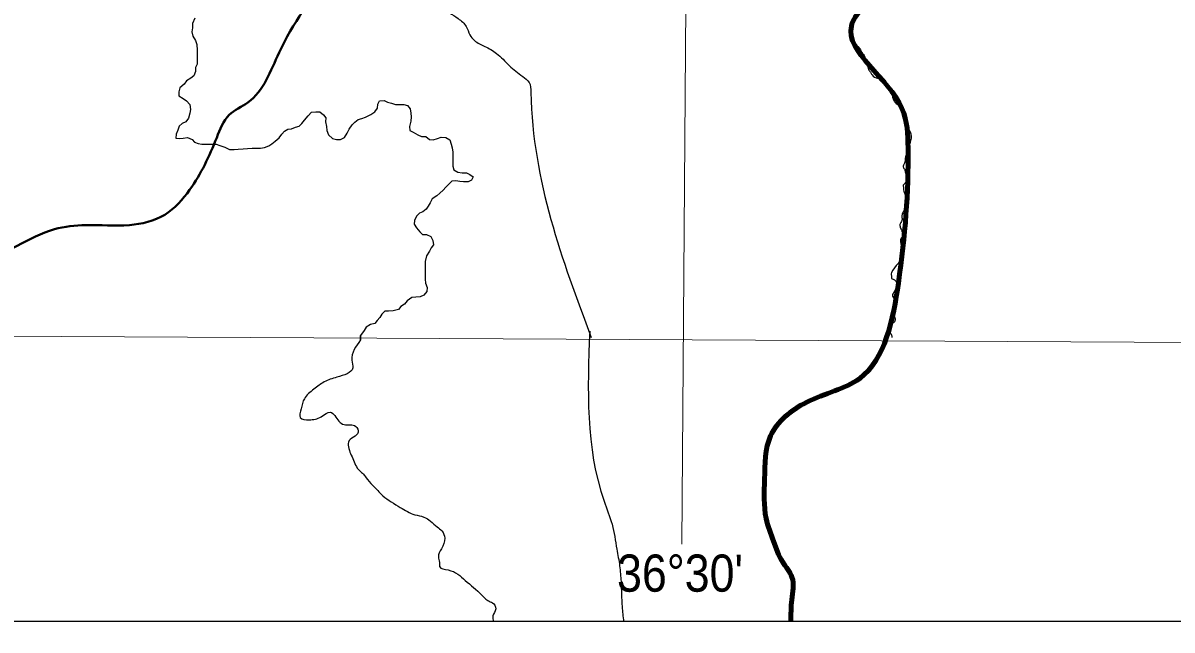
# Model space of a CAD drawing. Extents: x -1643653 to 4543381, y 1624270 to 13878484.
# Drawn here: x 765192 to 780645, y 8889723 to 8897887 of the extents above; entities that cross this region are included whole.
import ezdxf
from ezdxf.enums import TextEntityAlignment as Align

# ---------------------------------------------------------------- set-up
doc = ezdxf.new("R2010")
doc.units = 0
doc.header["$LTSCALE"] = 200
for name, color, linetype, lineweight in [('1', 7, 'Continuous', 13), ('12', 7, 'Continuous', 25), ('24', 7, 'Continuous', 25), ('3', 7, 'Continuous', 13), ('57', 7, 'Continuous', 13), ('60', 7, 'Continuous', 13), ('9', 7, 'Continuous', 90)]:
    doc.layers.add(name, color=color, linetype=linetype, lineweight=lineweight)
doc.layers.add('46', color=7, linetype='Continuous')

msp = doc.modelspace()

# ---------------------------------------------------------------- linework, layer by layer
at = {"layer": '1'}
for points in [[(774987.1, 9020818), (774482.3, 8948876), (774053.6, 8890875.3)], [(564751.7, 8894587.5), (664411.9, 8894209.9), (791388.5, 8893536.2)]]:
    msp.add_lwpolyline(points, dxfattribs=at)
at = {"layer": '12', "lineweight": 40}
msp.add_spline([(762623.9, 8893658.6), (765112.7, 8894889), (765616.1, 8895112.7), (766035.6, 8895168.6), (766622.8, 8895168.6), (767098.2, 8895308.5), (767433.8, 8895644), (767797.3, 8896343.2), (767965.1, 8896650.8), (768216.8, 8896818.6), (768636.3, 8897489.7), (769335.4, 8898552.4), (769698.9, 8899027.8), (770118.4, 8899810.8), (770454, 8900314.2), (770957.3, 8900677.7), (771712.4, 8900845.5), (772663.2, 8901013.3), (773474.2, 8900985.3), (774089.4, 8900957.3), (774760.5, 8900621.8), (775208, 8900454), (775431.7, 8900426), (775851.2, 8900733.6), (776242.7, 8901013.3), (776578.2, 8900985.3), (777025.7, 8900873.4), (777193.5, 8900929.4), (777277.3, 8901125.1), (777221.4, 8901460.7), (777277.3, 8901964.1), (777221.4, 8902439.5), (777081.6, 8902691.1), (777165.5, 8902914.9), (777417.2, 8903474.2), (777836.6, 8904201.2), (778228.2, 8904648.7), (778591.7, 8904956.3), (779254.3, 8905013.8), (779906, 8904928.3), (780814.8, 8904826.8)], degree=3, dxfattribs=at)
at = {"layer": '12'}
for points in [[(769589.5, 8898862.9), (770301.2, 8898417.1), (770809.5, 8898096.4), (771044.1, 8897947.8), (771153.6, 8897838.3), (771200.5, 8897728.9), (771263.1, 8897650.7), (771403.9, 8897572.4), (771560.3, 8897478.6), (771732.4, 8897314.4), (771912.2, 8897165.8), (771998.3, 8897087.6), (772021.7, 8896954.6), (772834.8, 8893656.6)], [(772814, 8893741.2), (773007.1, 8891454.9), (773113.6, 8891144.6), (773178.4, 8890810.2), (773216.5, 8890584.1), (773234.7, 8890374.1), (773248.5, 8890036.5), (773269.9, 8889836.8)]]:
    msp.add_spline(points, degree=3, dxfattribs=at)
at = {"layer": '24'}
for points in [[(767502.1, 8897951.1), (767471.1, 8897880), (767470.7, 8897824), (767465.2, 8897768), (767475, 8897711.9), (767510.2, 8897650.6), (767530.2, 8897599.5), (767534.8, 8897523), (767534.4, 8897461.9), (767533.9, 8897395.7), (767533.5, 8897334.6), (767512.8, 8897288.9)], [(767512.8, 8897288.9), (767512.4, 8897232.8), (767488, 8897175.6), (767450.1, 8897147.2), (767389.5, 8897111.4), (767358.7, 8897065.7), (767302.4, 8897015.2), (767286.8, 8896959.2), (767286.4, 8896908.3), (767347.2, 8896872.2), (767392.8, 8896841.4), (767438.2, 8896790.2), (767442.8, 8896723.9), (767437.4, 8896673), (767416.6, 8896606.9), (767380.6, 8896556.2), (767334.7, 8896536.1), (767293.8, 8896500.7), (767273.1, 8896444.8), (767252.4, 8896394), (767246.9, 8896338), (767297.7, 8896332.6), (767348.6, 8896337.4), (767404.6, 8896347.2), (767465.5, 8896321.3), (767500.8, 8896285.4), (767546.5, 8896264.8), (767597.3, 8896259.4), (767668.5, 8896258.9), (767719.4, 8896258.6), (767790.6, 8896258.1), (767841.3, 8896237.4), (767907.3, 8896216.6), (767968.1, 8896185.7), (768034.2, 8896185.2), (768085.1, 8896190), (768151.2, 8896194.7)], [(768151.2, 8896194.7), (768212.3, 8896199.4), (768273.4, 8896204.1), (768329.3, 8896203.7), (768385.3, 8896203.4), (768441.3, 8896213.2), (768497.4, 8896233.2), (768538.3, 8896263.5), (768584.3, 8896298.9), (768635.5, 8896344.4), (768671.4, 8896390), (768707.3, 8896430.5), (768753.2, 8896460.8), (768804.1, 8896465.6), (768855.1, 8896485.6), (768906.1, 8896500.6), (768942, 8896536), (768977.9, 8896581.6), (769029.1, 8896637.3), (769070.2, 8896688), (769131.2, 8896692.7), (769182.1, 8896692.4), (769232.7, 8896651.3), (769262.9, 8896610.3), (769262.5, 8896559.4), (769272.3, 8896493.1), (769277, 8896442.2), (769302, 8896380.9), (769352.6, 8896334.7), (769408.4, 8896319.1), (769464.3, 8896318.7), (769515.4, 8896348.9), (769551.4, 8896404.7), (769577.2, 8896460.6), (769618.3, 8896516.4), (769654.1, 8896551.8), (769700.1, 8896587.2), (769751.1, 8896602.1), (769797, 8896622.2), (769868.5, 8896657.4), (769924.7, 8896692.7), (769960.6, 8896743.4), (769966.1, 8896794.3), (769986.7, 8896840), (770047.8, 8896844.7), (770093.4, 8896824.1), (770149.2, 8896808.4), (770200, 8896792.8), (770256, 8896792.4), (770311.9, 8896792.1), (770362.7, 8896776.5), (770397.9, 8896730.4), (770407.7, 8896674.3), (770412.5, 8896623.3), (770407, 8896567.3), (770391.2, 8896496.1), (770395.9, 8896440.1), (770441.6, 8896419.4), (770502.4, 8896383.4), (770553.1, 8896362.7), (770609, 8896362.3), (770659.6, 8896321.2), (770710.4, 8896315.8), (770766.5, 8896335.8), (770817.5, 8896350.8)], [(770817.5, 8896350.8), (770878.5, 8896345.3), (770934.2, 8896314.4), (770949.1, 8896258.2), (770964, 8896207.2), (770973.8, 8896151.1), (770973.3, 8896079.8), (770972.9, 8896023.8), (770972.5, 8895962.7), (770987.4, 8895911.6), (771038, 8895880.7), (771099, 8895870.2), (771154.9, 8895869.8), (771200.6, 8895849.1), (771246.1, 8895818.3), (771225.5, 8895772.6), (771179.6, 8895752.5), (771118.5, 8895752.9), (771067.7, 8895753.2), (771011.8, 8895763.7), (770960.9, 8895759), (770914.8, 8895713.4), (770879, 8895678), (770843.1, 8895637.5), (770797, 8895597), (770756.1, 8895561.6), (770694.8, 8895521.3), (770669, 8895470.5), (770643.3, 8895424.8), (770612.5, 8895384.3), (770571.5, 8895348.9), (770525.6, 8895328.8), (770484.7, 8895288.3), (770458.8, 8895232.4), (770453.4, 8895181.5), (770483.6, 8895130.4), (770529, 8895079.2)], [(770529, 8895079.2), (770564.3, 8895043.3), (770620.3, 8895042.9), (770676.1, 8895017.1), (770706.2, 8894960.9), (770710.9, 8894904.8), (770680.1, 8894864.2), (770659.4, 8894818.5), (770618.3, 8894757.7), (770602.6, 8894681.4), (770602.1, 8894620.2), (770601.7, 8894559.1), (770601.3, 8894498), (770600.9, 8894442), (770605.6, 8894385.9), (770625.6, 8894329.8), (770625.2, 8894273.7), (770584.2, 8894228.1), (770533.1, 8894203), (770477.2, 8894198.3), (770421.2, 8894193.5), (770359.8, 8894148.1), (770324, 8894107.6), (770272.8, 8894072.2), (770242.1, 8894031.7), (770170.7, 8894016.8), (770109.7, 8894012.1), (770058.8, 8894012.5), (770017.8, 8893972), (769992.1, 8893926.3), (769956.2, 8893885.8), (769925.4, 8893845.2), (769864.3, 8893830.3), (769808.1, 8893795), (769782.3, 8893749.4), (769731, 8893683.5), (769730.6, 8893623.6), (769730.6, 8893623.6), (769731, 8893683.5)]]:
    msp.add_lwpolyline(points, dxfattribs=at)
for points in [[(776365.9, 8897887.4), (776337, 8897852.2), (776322, 8897817.1), (776310.7, 8897755.6), (776314.5, 8897724.2), (776345.8, 8897655.4), (776379.7, 8897601.5), (776422.3, 8897570.1), (776466.2, 8897507.3), (776502.6, 8897448.3), (776539, 8897370.5), (776552.8, 8897306.5), (776564.1, 8897265.1), (776587.9, 8897223.7), (776611.8, 8897188.5), (776684.5, 8897143.3), (776759.8, 8897134.6), (776784.9, 8897119.5), (776803.7, 8897075.6), (776837.6, 8897037.9), (776875.2, 8896999), (776882.7, 8896955.1), (776887.8, 8896884.8), (776899.1, 8896853.4), (776925, 8896814.1), (776977.7, 8896777.7), (777001.5, 8896757.6), (777016.6, 8896726.3), (777024.1, 8896688.6), (777030.3, 8896627.1), (777039.1, 8896585.7), (777056.7, 8896540.5), (777073, 8896504.1), (777101.9, 8896467.7), (777118.2, 8896433.8), (777133.2, 8896384.9), (777134.5, 8896338.4), (777128.2, 8896303.3), (777113.2, 8896253.1), (777096.8, 8896212.9), (777085.6, 8896182.8), (777065.4, 8896101.2), (777056.7, 8896071.1), (777056.7, 8896043.5), (777050.4, 8896017.1), (777040.3, 8895985.7), (777029.1, 8895963.1), (777031.6, 8895941.8), (777045.4, 8895923), (777057.9, 8895882.8), (777067.9, 8895833.9), (777067.9, 8895778.6), (777059.2, 8895742.2), (777040.3, 8895717.1), (777029.1, 8895705.8)], [(777029.1, 8895705.8), (777034.1, 8895656.9), (777037.8, 8895625.5), (777057.9, 8895576.6), (777080.5, 8895531.4), (777089.3, 8895497.5), (777085.5, 8895461.1), (777069.2, 8895412.1), (777051.6, 8895380.8), (777030.3, 8895349.4), (777017.8, 8895319.3), (777011.5, 8895297.9), (777015.2, 8895243.3), (777007.7, 8895217), (776988.9, 8895186.8), (776985.1, 8895163), (776990.1, 8895139.1), (777009, 8895096.5), (777021.5, 8895051.3), (777025.3, 8895023.7), (777002.7, 8894991), (776993.9, 8894953.4), (777001.4, 8894903.2), (776998.9, 8894847.9), (777001.4, 8894802.8), (777011.5, 8894772.7), (776873.4, 8894529.4), (776869.7, 8894500.5), (776873.4, 8894477.9), (776873.4, 8894449.1), (776896, 8894441.5), (776946.2, 8894401.4), (776968.8, 8894385.1), (776941.2, 8894328.6), (776893.5, 8894247), (776883.5, 8894226.9), (776894.7, 8894198), (776918.6, 8894176.7), (776948.7, 8894154.1), (776944.9, 8894129), (776931.1, 8894110.2), (776907.3, 8894075), (776887.2, 8894046.2), (776884.7, 8894021.1), (776893.5, 8893983.4), (776909.8, 8893950.8), (776916.1, 8893923.2), (776921.1, 8893893), (776912.3, 8893867.9), (776865.9, 8893832.8), (776847.1, 8893812.7), (776838.3, 8893767.5), (776840.8, 8893739.9), (776868.4, 8893699.8), (776877.2, 8893658.3)], [(769730.6, 8893623.6), (769616.5, 8893351.5), (769628.2, 8893248.9), (769414.9, 8893123.9), (769244.4, 8893058.7), (769103.4, 8892961.8), (768976.6, 8892833.6), (768931.1, 8892697.4), (768921.9, 8892580.3), (769038.2, 8892550.5), (769202.7, 8892590.4), (769327.2, 8892652.2), (769440.2, 8892530.6), (769510.1, 8892487.2), (769667.2, 8892461), (769700.2, 8892383.2), (769568.1, 8892250.2), (769566.7, 8892209.4), (769626.7, 8892028.4), (769718, 8891866.8), (769772.4, 8891818.8), (769806.4, 8891771.6), (769894.7, 8891671.3), (770032.5, 8891528.4), (770266.7, 8891371.7), (770462, 8891272.6), (770583.3, 8891242.6), (770673.2, 8891188.2), (770762.2, 8891108.4), (770826.6, 8891054.9), (770864, 8890956.5), (770818.3, 8890815.2), (770779, 8890709.4), (770791.6, 8890632.3), (770794.8, 8890576.1), (770910.4, 8890531), (771140.1, 8890389.8), (771362.6, 8890192.6), (771476.7, 8890101.6), (771506.9, 8890090.3), (771549.9, 8890007), (771510.9, 8889911.4), (771522.9, 8889836.8)]]:
    msp.add_spline(points, degree=3, dxfattribs=at)
at = {"layer": '3', "lineweight": 25}
msp.add_lwpolyline([(563033.9, 9026438.8), (793061.1, 9026438.8), (793495.6, 8889836.8), (563468.3, 8889836.8)], close=True, dxfattribs=at)
at = {"layer": '57'}
msp.add_lwpolyline([(724918, 8889836.8), (793495.6, 8889836.8), (793246.1, 8980523), (793207.5, 8980426.2)], dxfattribs=at)
at = {"layer": '60', "lineweight": 25}
msp.add_spline([(814781, 9009175.5), (814787.2, 9009173.4), (814796.9, 9009173.4), (814799.4, 9009172.4), (814805.1, 9009174.5), (814805.6, 9009176.5), (814811.7, 9009179.5), (814811.7, 9009179.5), (814801.5, 9009181), (814790.7, 9009181.5), (814784.1, 9009183.1), (814777.4, 9009185.1), (814778.4, 9009175.5)], degree=3, dxfattribs=at)
at = {"layer": '9'}
for points in [[(777421.5, 8899378.1), (777078.1, 8898719.8), (776715, 8898321.5), (776332.1, 8897844.8), (777012.8, 8896738.4), (777094.5, 8896207.1), (776964.6, 8894389.8), (776444.2, 8893106.5), (775732.1, 8892785.8), (775246.9, 8892335.8), (775165.8, 8891754.3), (775186.4, 8891222.2), (775285, 8890917.2), (775409.2, 8890637.1), (775534, 8890433), (775531.3, 8890129.1), (775519.2, 8889836.8)], [(777421.5, 8899378.1), (777078.1, 8898719.8), (776715, 8898321.5), (776332.1, 8897844.8), (777012.8, 8896738.4), (777094.5, 8896207.1), (776964.6, 8894389.8), (776444.2, 8893106.5), (775732.1, 8892785.8), (775246.9, 8892335.8), (775165.8, 8891754.3), (775186.4, 8891222.2), (775285, 8890917.2), (775409.2, 8890637.1), (775534, 8890433), (775531.3, 8890129.1), (775519.2, 8889836.8)], [(775519.2, 8889836.8), (775531.3, 8890129.1), (775534, 8890433), (775409.2, 8890637.1), (775285, 8890917.2), (775186.4, 8891222.2), (775165.8, 8891754.3), (775246.9, 8892335.8), (775732.1, 8892785.8), (776444.2, 8893106.5), (776964.6, 8894389.8), (777094.5, 8896207.1), (777012.8, 8896738.4), (776332.1, 8897844.8), (776715, 8898321.5), (777078.1, 8898719.8), (777421.5, 8899378.1)], [(777421.5, 8899378.1), (777078.1, 8898719.8), (776715, 8898321.5), (776332.1, 8897844.8), (777012.8, 8896738.4), (777094.5, 8896207.1), (776964.6, 8894389.8), (776444.2, 8893106.5), (775732.1, 8892785.8), (775246.9, 8892335.8), (775165.8, 8891754.3), (775186.4, 8891222.2), (775285, 8890917.2), (775409.2, 8890637.1), (775534, 8890433), (775531.3, 8890129.1), (775519.2, 8889836.8)]]:
    msp.add_spline(points, degree=3, dxfattribs=at)

# ---------------------------------------------------------------- texts
at = {"layer": '46', "width": 0.9}
msp.add_text("36°30'", height=500, dxfattribs=at).set_placement((774028.3, 8890238.2), align=Align.CENTER)

doc.saveas('drawing.dxf')
